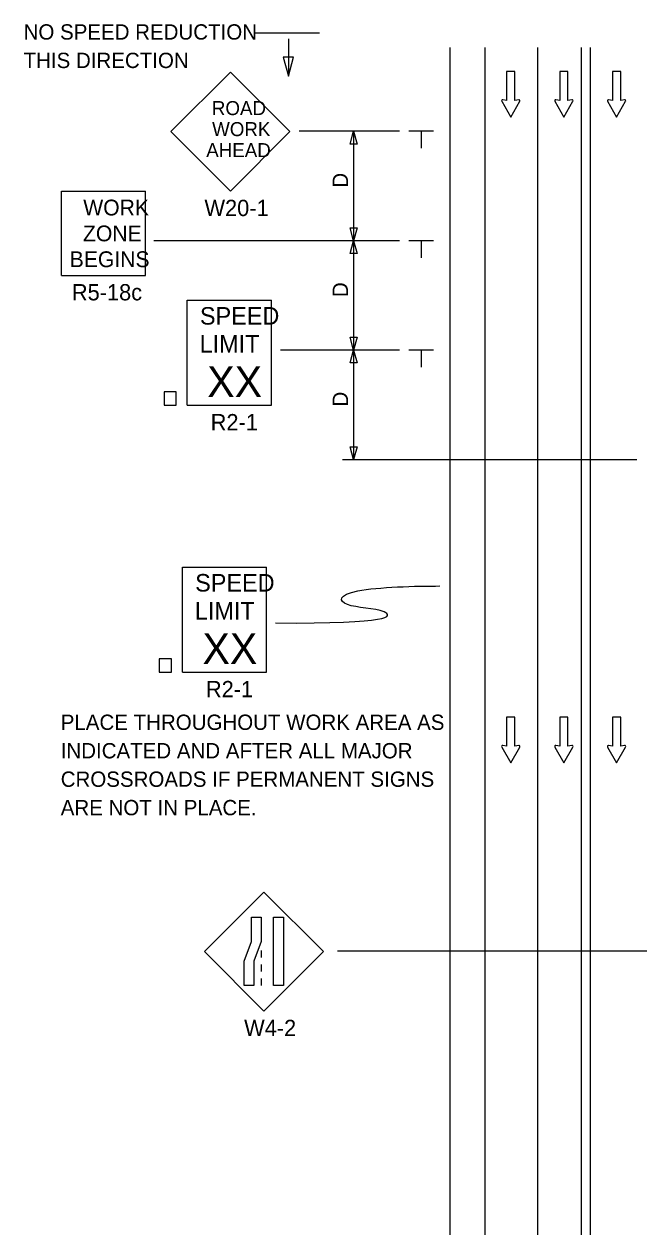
# Model space of a CAD drawing. Extents: x 16751 to 18475, y 5726 to 6923.
# Drawn here: x 16794 to 17074, y 6373 to 6923 of the extents above; entities that cross this region are included whole.
import ezdxf

# ---------------------------------------------------------------- set-up
doc = ezdxf.new("R2010")
doc.units = 0
for name, color, linetype in [('ALI_LEGAL_EX', 7, 'Continuous'), ('MT_SCRATCH_LEVEL_E', 7, 'Continuous'), ('PAVT_EDGE_EX', 7, 'Continuous'), ('TRAFFIC_SIGNS_PR', 7, 'Continuous'), ('TYPICAL_TEXT_DIMEN_PR', 7, 'Continuous')]:
    doc.layers.add(name, color=color, linetype=linetype)

msp = doc.modelspace()

# ---------------------------------------------------------------- linework, layer by layer
at = {"layer": 'ALI_LEGAL_EX'}
for p, q in [((17028.08, 6911.72), (17028.08, 6082.53)), ((17048.08, 6911.72), (17048.08, 6082.53)), ((17052.08, 6911.72), (17052.08, 6082.53))]:
    msp.add_line(p, q, dxfattribs=at)
for points in [[(17028.08, 6911.72), (17028.08, 6886.72)], [(17052.08, 6911.72), (17052.08, 6886.72)], [(17028.08, 6811.72), (17028.08, 6786.72)], [(17052.08, 6811.72), (17052.08, 6786.72)], [(17028.08, 6711.72), (17028.08, 6686.72)], [(17052.08, 6711.72), (17052.08, 6686.72)], [(17028.08, 6611.72), (17028.08, 6586.72)], [(17052.08, 6611.72), (17052.08, 6586.72)], [(17028.08, 6511.72), (17028.08, 6486.72)], [(17052.08, 6511.72), (17052.08, 6486.72)], [(17028.08, 6411.72), (17028.08, 6386.72)], [(17052.08, 6411.72), (17052.08, 6386.72)]]:
    msp.add_lwpolyline(points, dxfattribs=at)
at = {"layer": 'MT_SCRATCH_LEVEL_E'}
for p, q in [((17017.74, 6900.86), (17014, 6900.86)), ((17014, 6900.86), (17014, 6887.6)), ((17017.74, 6900.86), (17014, 6900.86)), ((17014, 6900.86), (17014, 6887.6)), ((17017.74, 6887.6), (17017.74, 6900.86)), ((17017.74, 6887.6), (17017.74, 6900.86)), ((17042, 6900.86), (17038.26, 6900.86)), ((17038.26, 6900.86), (17038.26, 6887.6)), ((17042, 6900.86), (17038.26, 6900.86)), ((17038.26, 6900.86), (17038.26, 6887.6)), ((17042, 6887.6), (17042, 6900.86)), ((17042, 6887.6), (17042, 6900.86)), ((17066.1, 6900.86), (17062.36, 6900.86)), ((17062.36, 6900.86), (17062.36, 6887.6)), ((17066.1, 6900.86), (17062.36, 6900.86)), ((17062.36, 6900.86), (17062.36, 6887.6)), ((17066.1, 6887.6), (17066.1, 6900.86)), ((17066.1, 6887.6), (17066.1, 6900.86)), ((17011.75, 6887.23), (17015.89, 6879.99)), ((17011.75, 6887.23), (17015.89, 6879.99)), ((17014, 6887.6), (17012.23, 6887.91)), ((17014, 6887.6), (17012.23, 6887.91)), ((17015.89, 6879.99), (17020, 6887.23)), ((17015.89, 6879.99), (17020, 6887.23)), ((17019.52, 6887.91), (17017.74, 6887.6)), ((17019.52, 6887.91), (17017.74, 6887.6)), ((17036, 6887.23), (17040.15, 6879.99)), ((17036, 6887.23), (17040.15, 6879.99)), ((17038.26, 6887.6), (17036.48, 6887.91)), ((17038.26, 6887.6), (17036.48, 6887.91)), ((17040.15, 6879.99), (17044.26, 6887.23)), ((17040.15, 6879.99), (17044.26, 6887.23)), ((17043.78, 6887.91), (17042, 6887.6)), ((17043.78, 6887.91), (17042, 6887.6)), ((17060.1, 6887.23), (17064.25, 6879.99)), ((17060.1, 6887.23), (17064.25, 6879.99)), ((17062.36, 6887.6), (17060.58, 6887.91)), ((17062.36, 6887.6), (17060.58, 6887.91)), ((17064.25, 6879.99), (17068.36, 6887.23)), ((17064.25, 6879.99), (17068.36, 6887.23)), ((17067.88, 6887.91), (17066.1, 6887.6)), ((17067.88, 6887.91), (17066.1, 6887.6)), ((17017.74, 6605.79), (17014, 6605.79)), ((17014, 6605.79), (17014, 6592.54)), ((17017.74, 6605.79), (17014, 6605.79)), ((17014, 6605.79), (17014, 6592.54)), ((17017.74, 6592.54), (17017.74, 6605.79)), ((17017.74, 6592.54), (17017.74, 6605.79)), ((17042, 6605.79), (17038.26, 6605.79)), ((17038.26, 6605.79), (17038.26, 6592.54)), ((17042, 6605.79), (17038.26, 6605.79)), ((17038.26, 6605.79), (17038.26, 6592.54)), ((17042, 6592.54), (17042, 6605.79)), ((17042, 6592.54), (17042, 6605.79)), ((17066.1, 6605.79), (17062.36, 6605.79)), ((17062.36, 6605.79), (17062.36, 6592.54)), ((17066.1, 6605.79), (17062.36, 6605.79)), ((17062.36, 6605.79), (17062.36, 6592.54)), ((17066.1, 6592.54), (17066.1, 6605.79)), ((17066.1, 6592.54), (17066.1, 6605.79)), ((17011.75, 6592.17), (17015.89, 6584.93)), ((17011.75, 6592.17), (17015.89, 6584.93)), ((17014, 6592.54), (17012.23, 6592.85)), ((17014, 6592.54), (17012.23, 6592.85)), ((17015.89, 6584.93), (17020, 6592.17)), ((17015.89, 6584.93), (17020, 6592.17)), ((17019.52, 6592.85), (17017.74, 6592.54)), ((17019.52, 6592.85), (17017.74, 6592.54)), ((17036, 6592.17), (17040.15, 6584.93)), ((17036, 6592.17), (17040.15, 6584.93)), ((17038.26, 6592.54), (17036.48, 6592.85)), ((17038.26, 6592.54), (17036.48, 6592.85)), ((17040.15, 6584.93), (17044.26, 6592.17)), ((17040.15, 6584.93), (17044.26, 6592.17)), ((17043.78, 6592.85), (17042, 6592.54)), ((17043.78, 6592.85), (17042, 6592.54)), ((17060.1, 6592.17), (17064.25, 6584.93)), ((17060.1, 6592.17), (17064.25, 6584.93)), ((17062.36, 6592.54), (17060.58, 6592.85)), ((17062.36, 6592.54), (17060.58, 6592.85)), ((17064.25, 6584.93), (17068.36, 6592.17)), ((17064.25, 6584.93), (17068.36, 6592.17)), ((17067.88, 6592.85), (17066.1, 6592.54)), ((17067.88, 6592.85), (17066.1, 6592.54))]:
    msp.add_line(p, q, dxfattribs=at)
for centre, start, end in [((17012.16, 6887.45), 80.0362, 209.7731), ((17012.16, 6887.45), 80.0362, 209.7731), ((17019.6, 6887.45), 330.4248, 99.9638), ((17019.6, 6887.45), 330.4248, 99.9638), ((17036.41, 6887.45), 80.0362, 209.7731), ((17036.41, 6887.45), 80.0362, 209.7731), ((17043.85, 6887.45), 330.4248, 99.9638), ((17043.85, 6887.45), 330.4248, 99.9638), ((17060.51, 6887.45), 80.0362, 209.7731), ((17060.51, 6887.45), 80.0362, 209.7731), ((17067.96, 6887.45), 330.4248, 99.9638), ((17067.96, 6887.45), 330.4248, 99.9638), ((17012.16, 6592.39), 80.0362, 209.7731), ((17012.16, 6592.39), 80.0362, 209.7731), ((17019.6, 6592.39), 330.4248, 99.9638), ((17019.6, 6592.39), 330.4248, 99.9638), ((17036.41, 6592.39), 80.0362, 209.7731), ((17036.41, 6592.39), 80.0362, 209.7731), ((17043.85, 6592.39), 330.4248, 99.9638), ((17043.85, 6592.39), 330.4248, 99.9638), ((17060.51, 6592.39), 80.0362, 209.7731), ((17060.51, 6592.39), 80.0362, 209.7731), ((17067.96, 6592.39), 330.4248, 99.9638), ((17067.96, 6592.39), 330.4248, 99.9638)]:
    msp.add_arc(centre, 0.463, start, end, dxfattribs=at)
at = {"layer": 'PAVT_EDGE_EX'}
for p, q in [((16988.08, 6911.72), (16988.08, 6082.53)), ((17004.08, 6911.72), (17004.08, 6082.53))]:
    msp.add_line(p, q, dxfattribs=at)
at = {"layer": 'TRAFFIC_SIGNS_PR'}
for p, q in [((16887.81, 6900.52), (16860.66, 6873.37)), ((16914.96, 6873.37), (16887.81, 6900.52)), ((16860.66, 6873.37), (16887.81, 6846.21)), ((16887.81, 6846.21), (16914.96, 6873.37)), ((16810.6, 6807.69), (16810.6, 6846.09)), ((16810.6, 6846.09), (16849, 6846.09)), ((16849, 6807.69), (16849, 6846.09)), ((16810.6, 6807.69), (16849, 6807.69)), ((16868.13, 6796.32), (16906.53, 6796.32)), ((16868.13, 6748.32), (16868.13, 6796.32)), ((16906.53, 6748.32), (16906.53, 6796.32)), ((16868.13, 6748.32), (16906.53, 6748.32)), ((16865.95, 6674.36), (16904.35, 6674.36)), ((16865.95, 6626.36), (16865.95, 6674.36)), ((16904.35, 6626.36), (16904.35, 6674.36)), ((16865.95, 6626.36), (16904.35, 6626.36)), ((16903.13, 6525.85), (16875.98, 6498.7)), ((16930.28, 6498.7), (16903.13, 6525.85)), ((16875.98, 6498.7), (16903.13, 6471.55)), ((16901.88, 6499.19), (16901.88, 6495.99)), ((16903.13, 6471.55), (16930.28, 6498.7)), ((16901.88, 6492.79), (16901.88, 6489.59)), ((16901.88, 6486.39), (16901.88, 6483.19))]:
    msp.add_line(p, q, dxfattribs=at)
for points in [[(16857.52, 6748.32), (16863.11, 6748.32), (16863.11, 6754.49), (16857.52, 6754.49)], [(16855.34, 6626.36), (16860.93, 6626.36), (16860.93, 6632.53), (16855.34, 6632.53)], [(16901.88, 6514.43), (16901.88, 6503.25), (16898.54, 6494.37), (16898.54, 6483.19), (16894.05, 6483.19), (16894.05, 6494.37), (16897.39, 6503.25), (16897.39, 6514.43)], [(16912.02, 6514.43), (16912.02, 6483.19), (16907.53, 6483.19), (16907.53, 6514.43)]]:
    msp.add_lwpolyline(points, close=True, dxfattribs=at)
at = {"layer": 'TYPICAL_TEXT_DIMEN_PR'}
for p, q in [((16928.51, 6918.28), (16899.07, 6918.28)), ((16914.34, 6915.78), (16914.34, 6898.66)), ((16914.34, 6907.45), (16911.98, 6907.45)), ((16911.98, 6907.45), (16914.34, 6898.66)), ((16914.34, 6898.66), (16916.69, 6907.45)), ((16916.69, 6907.45), (16914.34, 6907.45)), ((16965.08, 6873.53), (16919.23, 6873.53)), ((16942.51, 6867.67), (16944.08, 6873.53)), ((16944.08, 6873.53), (16944.08, 6823.53)), ((16944.08, 6873.53), (16945.65, 6867.67)), ((16980.58, 6873.53), (16969.33, 6873.53)), ((16974.95, 6873.53), (16974.95, 6865.75)), ((16944.08, 6867.67), (16942.51, 6867.67)), ((16945.65, 6867.67), (16944.08, 6867.67)), ((16944.08, 6823.53), (16942.51, 6829.39)), ((16942.51, 6829.39), (16944.08, 6829.39)), ((16944.08, 6829.39), (16945.65, 6829.39)), ((16945.65, 6829.39), (16944.08, 6823.53)), ((16965.08, 6823.53), (16852.9, 6823.53)), ((16942.51, 6817.67), (16944.08, 6823.53)), ((16944.08, 6823.53), (16944.08, 6773.53)), ((16944.08, 6823.53), (16945.65, 6817.67)), ((16980.58, 6823.53), (16969.33, 6823.53)), ((16974.95, 6823.53), (16974.95, 6815.75)), ((16944.08, 6817.67), (16942.51, 6817.67)), ((16945.65, 6817.67), (16944.08, 6817.67)), ((16944.08, 6773.53), (16942.51, 6779.39)), ((16942.51, 6779.39), (16944.08, 6779.39)), ((16944.08, 6779.39), (16945.65, 6779.39)), ((16945.65, 6779.39), (16944.08, 6773.53)), ((16965.08, 6773.53), (16910.77, 6773.53)), ((16942.51, 6767.67), (16944.08, 6773.53)), ((16944.08, 6773.53), (16944.08, 6723.53)), ((16944.08, 6773.53), (16945.65, 6767.67)), ((16980.58, 6773.53), (16969.33, 6773.53)), ((16974.95, 6773.53), (16974.95, 6765.75)), ((16944.08, 6767.67), (16942.51, 6767.67)), ((16945.65, 6767.67), (16944.08, 6767.67)), ((16944.08, 6723.53), (16942.51, 6729.39)), ((16942.51, 6729.39), (16944.08, 6729.39)), ((16944.08, 6729.39), (16945.65, 6729.39)), ((16945.65, 6729.39), (16944.08, 6723.53)), ((16939.08, 6723.53), (17073.46, 6723.53)), ((16936.74, 6499), (17084.27, 6499))]:
    msp.add_line(p, q, dxfattribs=at)
msp.add_open_spline([(16908.35, 6648.85), (16962.23, 6648.45), (16962.23, 6655.71), (16937.05, 6655.71), (16937.05, 6664.82), (16972.96, 6665.77), (16983.48, 6665.75)], degree=3, dxfattribs=at)

# ---------------------------------------------------------------- texts
at = {"layer": 'TRAFFIC_SIGNS_PR'}
for s, height, p in [('ROAD', 6.4, (16879.35, 6880.9)), ('WORK', 6.4, (16879.46, 6871.3)), ('AHEAD', 6.4, (16876.77, 6861.7)), ('WORK', 7.217, (16820.6, 6835.06)), ('W20-1', 7.44, (16875.98, 6834.77)), ('ZONE', 7.217, (16820.48, 6823.24)), ('BEGINS', 7.217, (16814.41, 6811.44)), ('R5-18c', 7.44, (16815.41, 6796.25)), ('SPEED', 8, (16873.9, 6785.18)), ('LIMIT', 8, (16873.74, 6772.38)), ('XX', 14.031, (16877.24, 6752.08)), ('R2-1', 7.44, (16878.81, 6736.88)), ('SPEED', 8, (16871.72, 6663.22)), ('LIMIT', 8, (16871.56, 6650.42)), ('XX', 14.031, (16875.06, 6630.12)), ('R2-1', 7.44, (16876.63, 6614.92)), ('PLACE THROUGHOUT WORK AREA AS', 7, (16810.31, 6599.99)), ('INDICATED AND AFTER ALL MAJOR', 7, (16810.31, 6586.99)), ('CROSSROADS IF PERMANENT SIGNS', 7, (16810.31, 6573.99)), ('ARE NOT IN PLACE.', 7, (16810.31, 6560.99)), ('W4-2', 7.44, (16894.09, 6460.11))]:
    msp.add_text(s, height=height, dxfattribs=at).set_placement(p)
at = {"layer": 'TYPICAL_TEXT_DIMEN_PR'}
for s, p in [('NO SPEED REDUCTION', (16793.35, 6915.4)), ('THIS DIRECTION', (16793.35, 6902.4))]:
    msp.add_text(s, height=7, dxfattribs=at).set_placement(p)
for p in [(16941.52, 6847.75), (16941.52, 6797.75), (16941.52, 6747.75)]:
    msp.add_text('D', height=7, rotation=90, dxfattribs=at).set_placement(p)

doc.saveas('drawing.dxf')
